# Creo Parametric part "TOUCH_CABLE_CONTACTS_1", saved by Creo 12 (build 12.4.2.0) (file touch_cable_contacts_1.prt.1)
Units: Custom; MM, KILOGRAM, SECS

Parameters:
  PTC_WM_ITERATION = "0"
  PTC_WM_VERSION = "-.0"
  PTC_WM_LIFECYCLE_STATE = "In Work"
  PTC_WM_LIFECYCLE = "MO_CADDocument"
  PTC_WM_CREATED_BY = "Maximilian Roepper (Z0017RMS: MO)"
  PTC_WM_CREATED_ON = "18-Sep-26 11:36:42 AM"
  PTC_WM_MODIFIED_BY = "Maximilian Roepper (Z0017RMS: MO)"
  PTC_WM_MODIFIED_ON = "18-Sep-26 11:36:46 AM"
  PDMLINKNUMBER = "PDM000071455277"
  PTC_WM_NAME = "touch_cable_contacts_1.prt"
  PTC_WM_NUMBER = "PDM000071455277"

Other parameters: WEIGHT, WEIGHT_FACTOR, WEIGHT_ADD, _MASS_TEMP, _DIFF_TEMP, MC_ERRORS, SUPPLIER

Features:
  1. coordinate system
  2. datum plane "PRT_YZ"
  3. datum plane "PRT_XY"
  4. datum plane "PRT_XZ"
  5. coordinate system
  6. datum axis
  7. datum axis
  8. datum axis
  9. coordinate system
  10. imported feature
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
Other named items: PRT, SIEMENS_MO, DRW_VIEW_ORG, PRT_X, PRT_Y, PRT_Z, CS0, ROUGH_GROB

Layers: 00_STD_CSYS-KSYS, 01_STD_PLANES-EBENEN, 02_STD_AXES-ACHSEN, 03_STD_CSYS-KSYS, 24_IMPORT_FEAT-IMPORT_KE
